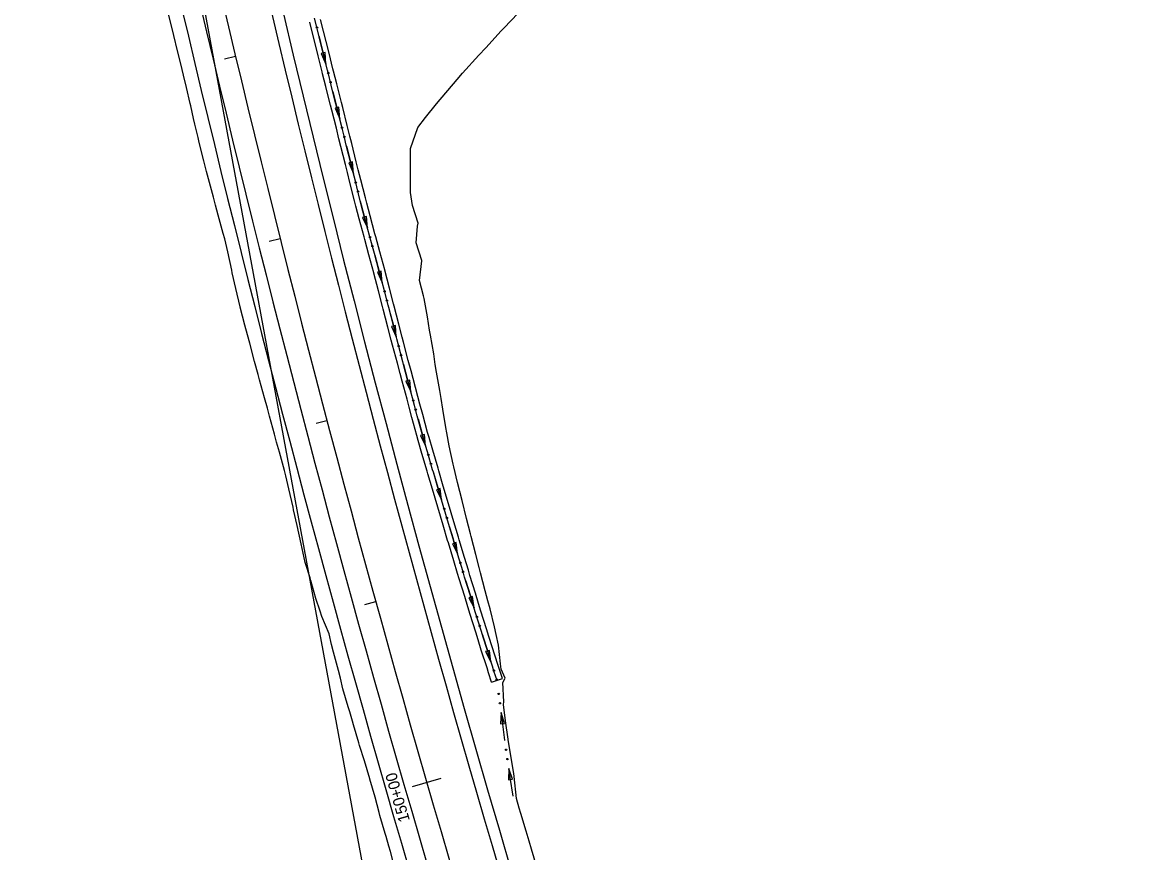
# Model space of a CAD drawing. Extents: x 948761 to 996004, y 1858548 to 1925175.
# Drawn here: x 986412 to 987000, y 1872130 to 1872573 of the extents above; entities that cross this region are included whole.
import ezdxf

# ---------------------------------------------------------------- set-up
doc = ezdxf.new("R2010")
doc.units = 0
for name, color, linetype in [('62', 7, 'Continuous'), ('R_Horz Alg', 7, 'Continuous'), ('R_Horz Alg Annot', 7, 'Continuous'), ('R_Proposed Const Limits', 7, 'Continuous'), ('R_Proposed Road', 7, 'Continuous')]:
    doc.layers.add(name, color=color, linetype=linetype)

msp = doc.modelspace()

# ---------------------------------------------------------------- linework, layer by layer
at = {"layer": '62'}
for p, q in [((986573.16, 1872556.61), (986571.11, 1872556.1)), ((986571.11, 1872556.1), (986573.6, 1872550.54)), ((986573.6, 1872550.54), (986573.16, 1872556.61)), ((986580.5, 1872527.49), (986578.45, 1872526.97)), ((986578.45, 1872526.97), (986580.95, 1872521.41)), ((986580.95, 1872521.41), (986580.5, 1872527.49)), ((986587.8, 1872498.35), (986585.75, 1872497.83)), ((986585.75, 1872497.83), (986588.23, 1872492.27)), ((986588.23, 1872492.27), (986587.8, 1872498.35)), ((986595.2, 1872469.25), (986593.16, 1872468.71)), ((986593.16, 1872468.71), (986595.74, 1872463.19)), ((986595.74, 1872463.19), (986595.2, 1872469.25)), ((986603.04, 1872440.25), (986600.99, 1872439.71)), ((986603.54, 1872434.18), (986603.04, 1872440.25)), ((986600.99, 1872439.71), (986603.54, 1872434.18)), ((986610.6, 1872411.18), (986608.56, 1872410.65)), ((986611.09, 1872405.11), (986610.6, 1872411.18)), ((986608.56, 1872410.65), (986611.09, 1872405.11)), ((986618.24, 1872382.14), (986616.2, 1872381.59)), ((986616.2, 1872381.59), (986618.77, 1872376.07)), ((986618.77, 1872376.07), (986618.24, 1872382.14)), ((986626.03, 1872353.15), (986624, 1872352.56)), ((986624, 1872352.56), (986626.7, 1872347.09)), ((986626.7, 1872347.09), (986626.03, 1872353.15)), ((986634.48, 1872324.33), (986632.45, 1872323.73)), ((986632.45, 1872323.73), (986635.16, 1872318.27)), ((986635.16, 1872318.27), (986634.48, 1872324.33)), ((986643.04, 1872295.54), (986641.02, 1872294.93)), ((986641.02, 1872294.93), (986643.76, 1872289.49)), ((986643.76, 1872289.49), (986643.04, 1872295.54)), ((986651.74, 1872266.8), (986649.72, 1872266.17)), ((986649.72, 1872266.17), (986652.5, 1872260.75)), ((986652.5, 1872260.75), (986651.74, 1872266.8)), ((986660.66, 1872238.13), (986658.65, 1872237.48)), ((986658.65, 1872237.48), (986661.49, 1872232.09)), ((986661.49, 1872232.09), (986660.66, 1872238.13)), ((986661.88, 1872221.2), (986667.58, 1872223.07)), ((986666.94, 1872205.02), (986666.66, 1872198.94)), ((986668.76, 1872199.21), (986666.94, 1872205.02)), ((986666.66, 1872198.94), (986668.76, 1872199.21)), ((986671.07, 1872175.27), (986670.89, 1872169.18)), ((986670.89, 1872169.18), (986672.99, 1872169.49)), ((986672.99, 1872169.49), (986671.07, 1872175.27))]:
    msp.add_line(p, q, dxfattribs=at)
for points in [[(986661.88, 1872221.2), (986660.26, 1872226.14), (986659.4, 1872228.78), (986656.36, 1872238.27), (986654.64, 1872243.77), (986653.39, 1872247.78), (986650.44, 1872257.28), (986649.16, 1872261.4), (986647.5, 1872266.79), (986644.59, 1872276.31), (986643.76, 1872279.07), (986641.72, 1872285.84), (986638.86, 1872295.37), (986638.44, 1872296.75), (986636.01, 1872304.91), (986633.17, 1872314.44), (986633.16, 1872314.45), (986630.35, 1872323.99), (986627.95, 1872332.16), (986627.55, 1872333.54), (986624.75, 1872343.08), (986622.76, 1872349.9), (986621.97, 1872352.69), (986619.37, 1872362.3), (986617.91, 1872367.75), (986616.78, 1872371.9), (986614.21, 1872381.52), (986613.12, 1872385.59), (986611.64, 1872391.13), (986609.12, 1872400.76), (986608.42, 1872403.45), (986606.62, 1872410.39), (986604.12, 1872420.02), (986603.78, 1872421.33), (986601.64, 1872429.65), (986599.13, 1872439.16), (986599.11, 1872439.23), (986596.5, 1872448.84), (986594.31, 1872456.97), (986593.91, 1872458.44), (986591.32, 1872468.06), (986589.53, 1872474.83), (986588.8, 1872477.72), (986586.37, 1872487.37), (986585.02, 1872492.75), (986583.95, 1872497.02), (986581.54, 1872506.67), (986580.55, 1872510.67), (986579.15, 1872516.32), (986576.71, 1872525.95), (986576.05, 1872528.55), (986574.26, 1872535.6), (986573.51, 1872538.58), (986571.83, 1872545.25), (986571.53, 1872546.46), (986569.41, 1872554.9), (986564.95, 1872572.89)], [(986664.73, 1872222.14), (986663.11, 1872227.07), (986662.25, 1872229.7), (986659.22, 1872239.18), (986657.5, 1872244.66), (986656.25, 1872248.67), (986653.31, 1872258.17), (986652.03, 1872262.29), (986650.36, 1872267.67), (986647.46, 1872277.18), (986646.63, 1872279.94), (986644.59, 1872286.71), (986641.73, 1872296.23), (986641.32, 1872297.61), (986638.88, 1872305.76), (986636.04, 1872315.3), (986636.04, 1872315.3), (986633.22, 1872324.84), (986630.83, 1872333.01), (986630.42, 1872334.38), (986627.63, 1872343.93), (986625.64, 1872350.72), (986624.87, 1872353.48), (986622.27, 1872363.08), (986620.8, 1872368.54), (986619.68, 1872372.68), (986617.1, 1872382.29), (986616.02, 1872386.36), (986614.54, 1872391.9), (986612.02, 1872401.52), (986611.32, 1872404.21), (986609.52, 1872411.15), (986607.02, 1872420.77), (986606.69, 1872422.07), (986604.54, 1872430.4), (986602.03, 1872439.93), (986602, 1872440.02), (986599.4, 1872449.62), (986597.2, 1872457.75), (986596.81, 1872459.22), (986594.22, 1872468.83), (986592.43, 1872475.58), (986591.71, 1872478.45), (986589.28, 1872488.1), (986587.93, 1872493.48), (986586.86, 1872497.75), (986584.46, 1872507.4), (986583.46, 1872511.39), (986582.06, 1872517.05), (986579.61, 1872526.69), (986578.95, 1872529.29), (986577.17, 1872536.33), (986576.42, 1872539.31), (986574.74, 1872545.98), (986574.44, 1872547.19), (986572.32, 1872555.63), (986570.71, 1872562.1), (986569.98, 1872565.1), (986569.93, 1872565.28), (986567.56, 1872574.94)], [(986667.58, 1872223.07), (986665.97, 1872228.01), (986665.11, 1872230.63), (986662.08, 1872240.08), (986660.37, 1872245.55), (986659.12, 1872249.56), (986656.17, 1872259.06), (986654.9, 1872263.17), (986653.23, 1872268.55), (986650.33, 1872278.05), (986649.5, 1872280.8), (986647.47, 1872287.57), (986644.6, 1872297.09), (986644.19, 1872298.47), (986641.76, 1872306.62), (986638.92, 1872316.15), (986638.92, 1872316.15), (986636.1, 1872325.68), (986633.71, 1872333.85), (986633.3, 1872335.23), (986630.51, 1872344.77), (986628.52, 1872351.55), (986627.76, 1872354.28), (986625.17, 1872363.86), (986623.7, 1872369.32), (986622.58, 1872373.46), (986620, 1872383.07), (986618.92, 1872387.13), (986617.44, 1872392.67), (986614.93, 1872402.28), (986614.23, 1872404.97), (986612.42, 1872411.9), (986609.93, 1872421.53), (986609.59, 1872422.82), (986607.44, 1872431.16), (986604.92, 1872440.71), (986604.9, 1872440.81), (986602.29, 1872450.4), (986600.1, 1872458.53), (986599.7, 1872460), (986597.12, 1872469.6), (986595.34, 1872476.33), (986594.62, 1872479.19), (986592.19, 1872488.83), (986590.84, 1872494.21), (986589.77, 1872498.47), (986587.37, 1872508.12), (986586.37, 1872512.11), (986584.97, 1872517.78), (986582.52, 1872527.43), (986581.86, 1872530.03), (986580.08, 1872537.07), (986579.33, 1872540.05), (986577.65, 1872546.71), (986577.35, 1872547.92), (986575.23, 1872556.35), (986570.77, 1872574.32)], [(986569.97, 1872565.13), (986569.98, 1872565.1), (986569.98, 1872565.09)], [(986569.98, 1872565.09), (986570.71, 1872562.1), (986572.32, 1872555.63), (986573.6, 1872550.54)], [(986577.26, 1872535.99), (986577.27, 1872535.95)], [(986577.27, 1872535.95), (986578.95, 1872529.29), (986579.61, 1872526.69), (986580.95, 1872521.41)], [(986584.59, 1872506.86), (986584.6, 1872506.82)], [(986584.6, 1872506.82), (986586.86, 1872497.75), (986587.93, 1872493.48), (986588.23, 1872492.27)], [(986591.89, 1872477.72), (986591.9, 1872477.69)], [(986591.9, 1872477.69), (986592.43, 1872475.58), (986594.22, 1872468.83), (986595.74, 1872463.19)], [(986599.65, 1872448.7), (986599.66, 1872448.67)], [(986599.66, 1872448.67), (986602, 1872440.02), (986602.03, 1872439.93), (986603.54, 1872434.18)], [(986607.31, 1872419.66), (986607.32, 1872419.62)], [(986607.32, 1872419.62), (986609.52, 1872411.15), (986611.09, 1872405.11)], [(986614.89, 1872390.59), (986614.9, 1872390.56)], [(986614.9, 1872390.56), (986616.02, 1872386.36), (986617.1, 1872382.29), (986618.77, 1872376.07)], [(986622.68, 1872361.58), (986622.69, 1872361.55)], [(986622.69, 1872361.55), (986624.87, 1872353.48), (986625.64, 1872350.72), (986626.7, 1872347.09)], [(986630.92, 1872332.7), (986630.93, 1872332.66)], [(986630.93, 1872332.66), (986633.22, 1872324.84), (986635.16, 1872318.27)], [(986639.44, 1872303.9), (986639.45, 1872303.86)], [(986639.45, 1872303.86), (986641.32, 1872297.61), (986641.73, 1872296.23), (986643.76, 1872289.49)], [(986648.09, 1872275.13), (986648.1, 1872275.09)], [(986648.1, 1872275.09), (986650.36, 1872267.67), (986652.03, 1872262.29), (986652.5, 1872260.75)], [(986656.95, 1872246.43), (986656.96, 1872246.39)], [(986656.96, 1872246.39), (986657.5, 1872244.66), (986659.22, 1872239.18), (986661.49, 1872232.09)], [(986668.89, 1872190.15), (986668.88, 1872190.23), (986668.87, 1872190.34), (986667.57, 1872200.2), (986666.94, 1872205.02)], [(986668.9, 1872190.11), (986668.89, 1872190.15)], [(986673.26, 1872160.43), (986671.79, 1872170.37), (986671.56, 1872171.9), (986671.07, 1872175.27)]]:
    msp.add_lwpolyline(points, dxfattribs=at)
for centre in [(986568.82, 1872569.98), (986574.85, 1872545.69), (986576.08, 1872540.83), (986582.22, 1872516.57), (986583.42, 1872511.71), (986589.49, 1872487.42), (986590.71, 1872482.57), (986597.08, 1872458.36), (986598.38, 1872453.52), (986604.85, 1872429.35), (986606.1, 1872424.5), (986612.39, 1872400.27), (986613.66, 1872395.42), (986620.11, 1872371.24), (986621.41, 1872366.4), (986628.14, 1872342.3), (986629.55, 1872337.49), (986636.62, 1872313.48), (986638.05, 1872308.68), (986645.23, 1872284.71), (986646.68, 1872279.91), (986654.02, 1872255.98), (986655.51, 1872251.2), (986663.07, 1872227.34), (986664.62, 1872222.58), (986665.62, 1872214.95), (986666.26, 1872209.98), (986669.58, 1872185.18), (986670.31, 1872180.22)]:
    msp.add_circle(centre, 0.375, dxfattribs=at)
at = {"layer": 'R_Horz Alg'}
msp.add_arc((994885.09, 1874549.52), 8594.37, 190.453455, 203.072581, dxfattribs=at)
at = {"layer": 'R_Horz Alg Annot'}
msp.add_line((986605.79, 1872055.68), (986480.9, 1872732.56), dxfattribs=at)
for points in [[(986519.61, 1872553.28), (986525.45, 1872554.67)], [(986543.4, 1872456.08), (986549.22, 1872457.54)], [(986568.32, 1872359.16), (986574.13, 1872360.69)], [(986594.37, 1872262.54), (986600.16, 1872264.14)], [(986619.62, 1872165.68), (986635, 1872170.11)]]:
    msp.add_lwpolyline(points, dxfattribs=at)
at = {"layer": 'R_Proposed Const Limits'}
for points in [[(986610.53, 1872121.28), (986607.94, 1872130.98), (986607.14, 1872133.87), (986605.66, 1872138.94), (986605.13, 1872140.61), (986602.25, 1872150.22), (986601.94, 1872151.75), (986599.88, 1872159.98), (986596.94, 1872169.57), (986596.91, 1872169.67), (986594.07, 1872179.19), (986591.54, 1872187.51), (986591.15, 1872188.79), (986588.32, 1872198.42), (986587.74, 1872200.34), (986586.24, 1872205.36), (986585.45, 1872208.03), (986582.66, 1872217.67), (986581.29, 1872223.31), (986580.3, 1872227.43), (986577.61, 1872237.1), (986576.61, 1872241.33), (986575.32, 1872246.88), (986571.48, 1872256.22), (986570.54, 1872258.97), (986568.24, 1872265.74), (986565.59, 1872275.42), (986565.14, 1872276.8), (986562.46, 1872284.97), (986560.42, 1872294.81), (986560.42, 1872294.82), (986558.2, 1872304.61), (986556.37, 1872313.02), (986556.06, 1872314.42), (986553.89, 1872324.23), (986552.32, 1872331.21), (986551.6, 1872334.01), (986548.86, 1872343.66), (986547.33, 1872349.15), (986546.2, 1872353.33), (986543.51, 1872363), (986542.38, 1872367.1), (986540.89, 1872372.69), (986538.23, 1872382.36), (986537.5, 1872385.07), (986535.6, 1872392.05), (986533, 1872401.74), (986532.65, 1872403.05), (986530.39, 1872411.43), (986527.89, 1872421.05), (986527.87, 1872421.14), (986525.68, 1872430.94), (986523.72, 1872439.21), (986523.4, 1872440.71), (986521.28, 1872450.52), (986519.65, 1872457.38), (986518.86, 1872460.26), (986516.21, 1872469.94), (986514.76, 1872475.35), (986513.63, 1872479.64), (986511.04, 1872489.34), (986509.97, 1872493.35), (986508.49, 1872499.04), (986506.14, 1872508.8), (986505.51, 1872511.43), (986503.83, 1872518.56), (986503.12, 1872521.58), (986501.55, 1872528.33), (986501.26, 1872529.56), (986499.29, 1872538.11), (986497.77, 1872544.67), (986496.99, 1872547.68), (986496.94, 1872547.87), (986494.47, 1872557.59), (986492.53, 1872565.76), (986492.15, 1872567.35), (986489.72, 1872577.09)], [(986675.13, 1872159.16), (986673.89, 1872170.97), (986673.63, 1872172.5), (986672.24, 1872180.85), (986670.61, 1872190.73), (986670.59, 1872190.83), (986669.17, 1872200.66), (986668.24, 1872209.35), (986668.31, 1872210.75), (986667.88, 1872220.96), (986669.02, 1872223.35), (986666.89, 1872228.14), (986666.54, 1872230.91), (986665.47, 1872240.93), (986664.25, 1872246.55), (986663.37, 1872250.66), (986661.05, 1872260.32), (986659.92, 1872264.48), (986658.44, 1872269.91), (986655.89, 1872279.51), (986655.18, 1872282.29), (986653.43, 1872289.13), (986650.95, 1872298.75), (986650.59, 1872300.15), (986648.52, 1872308.39), (986646.08, 1872318.02), (986646.08, 1872318.02), (986643.7, 1872327.66), (986641.7, 1872335.93), (986641.35, 1872337.31), (986639.29, 1872347.04), (986638.01, 1872354.02), (986637.54, 1872356.85), (986635.83, 1872366.67), (986634.97, 1872372.28), (986634.32, 1872376.54), (986632.55, 1872386.34), (986631.87, 1872390.51), (986630.99, 1872396.19), (986629.36, 1872406.02), (986628.82, 1872408.75), (986627.71, 1872415.85), (986625.99, 1872425.65), (986625.64, 1872426.95), (986623.51, 1872435.26), (986624.63, 1872445.69), (986624.6, 1872445.78), (986621.7, 1872455.27), (986622.42, 1872464.11), (986622.66, 1872465.75), (986619.74, 1872475.23), (986618.73, 1872482.16), (986618.71, 1872485.2), (986618.65, 1872495.4), (986618.64, 1872501.09), (986618.62, 1872505.6), (986622.58, 1872516.78), (986626.64, 1872521.99), (986632.42, 1872529.38), (986643.55, 1872542.26), (986646.39, 1872545.69), (986655.12, 1872555.22), (986658.71, 1872559.22), (986666.9, 1872568.2), (986668.5, 1872569.85), (986679.55, 1872581.35)], [(986723.64, 1872053.74), (986708.69, 1872050.03), (986705.86, 1872055.94), (986705.64, 1872056.46), (986702.93, 1872065.45), (986702.87, 1872065.64), (986700.14, 1872075), (986697.72, 1872083.37), (986697.38, 1872084.56), (986696.67, 1872087.06), (986694.66, 1872094.13), (986692.57, 1872101.1), (986691.81, 1872103.66), (986688.94, 1872113.19), (986687.22, 1872118.77), (986686.01, 1872122.7), (986683.09, 1872132.21), (986681.81, 1872136.42), (986680.22, 1872141.74), (986677.42, 1872151.28), (986676.59, 1872154.13), (986675.13, 1872159.16)]]:
    msp.add_lwpolyline(points, dxfattribs=at)
at = {"layer": 'R_Proposed Road'}
for radius, end in [(8570.37, 203.072581), (8564.37, 200.088068), (8606.37, 203.072581), (8616.37, 203.072581)]:
    msp.add_arc((994885.09, 1874549.52), radius, 190.453455, end, dxfattribs=at)

# ---------------------------------------------------------------- texts
at = {"layer": 'R_Horz Alg Annot'}
msp.add_text('150+00', height=6, rotation=106.08807, dxfattribs=at).set_placement((986618.37, 1872147.62))

doc.saveas('drawing.dxf')
